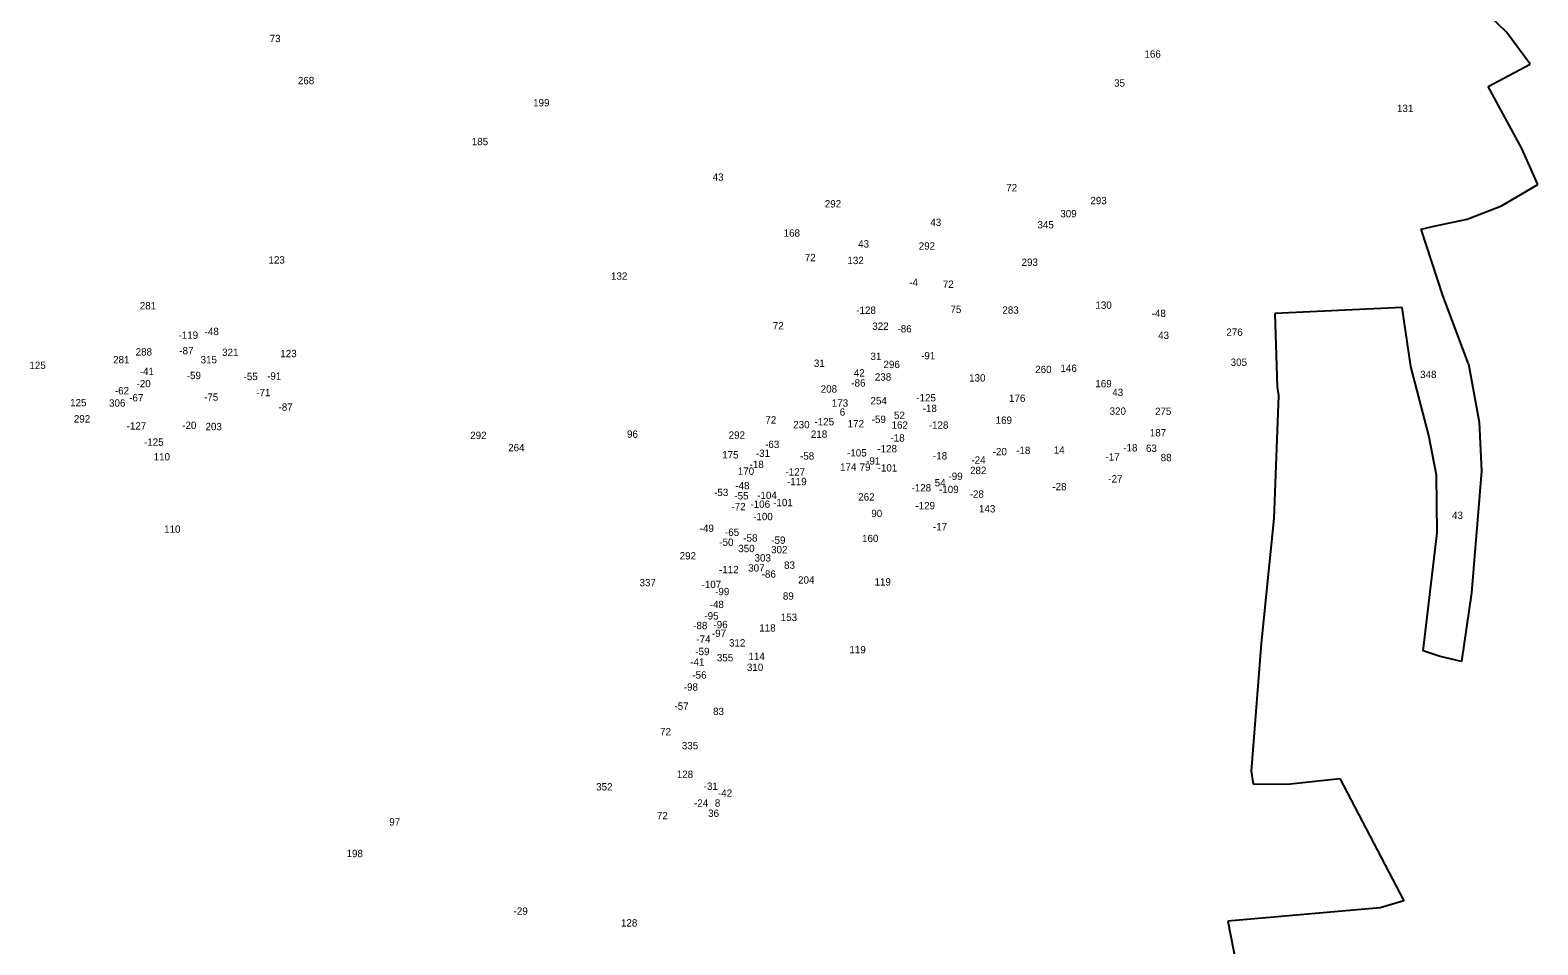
# Model space of a CAD drawing. Extents: x -780116 to -776974, y -980293 to -977147.
# Drawn here: x -778638 to -777335, y -979511 to -978721 of the extents above; entities that cross this region are included whole.
import ezdxf

# ---------------------------------------------------------------- set-up
doc = ezdxf.new("R2010")
doc.units = 0
for name, color, linetype in [('Vrstva 13', 7, 'Continuous'), ('Vrstva 15', 7, 'Continuous'), ('Vrstva 24', 7, 'Continuous')]:
    doc.layers.add(name, color=color, linetype=linetype)

msp = doc.modelspace()

# ---------------------------------------------------------------- linework, layer by layer
at = {"layer": 'Vrstva 13'}
for p, q in [((-777362.22, -978722.53), (-777377.55, -978707.5)), ((-777341.72, -978750.16), (-777362.22, -978722.53)), ((-777377.92, -978769.56), (-777341.72, -978750.16)), ((-777348.79, -978822.96), (-777377.92, -978769.56)), ((-777334.99, -978854.28), (-777348.79, -978822.96)), ((-777366.3, -978872.5), (-777334.99, -978854.28)), ((-777396.05, -978884.27), (-777366.3, -978872.5)), ((-777423.29, -978889.9), (-777396.05, -978884.27)), ((-777435.87, -978892.86), (-777423.29, -978889.9)), ((-777417.23, -978950.19), (-777435.87, -978892.86)), ((-777394.87, -979008.99), (-777417.23, -978950.19))]:
    msp.add_line(p, q, dxfattribs=at)
at = {"layer": 'Vrstva 15'}
for p, q in [((-777452.25, -978960.55), (-777562.39, -978965.5)), ((-777562.39, -978965.5), (-777560.35, -979029.05)), ((-777444.67, -979011.56), (-777452.25, -978960.55)), ((-777429.23, -979071.02), (-777444.67, -979011.56)), ((-777394.87, -979008.99), (-777385.81, -979059.43)), ((-777560.35, -979029.05), (-777559.18, -979036.34)), ((-777559.18, -979036.34), (-777563.26, -979142.8)), ((-777422.67, -979105.2), (-777429.23, -979071.02)), ((-777385.81, -979059.43), (-777383.77, -979101.99)), ((-777421.94, -979155.11), (-777422.67, -979105.2)), ((-777383.77, -979101.99), (-777392.37, -979207.08)), ((-777563.26, -979142.8), (-777574.04, -979250.73)), ((-777434.03, -979257.03), (-777421.94, -979155.11)), ((-777392.37, -979207.08), (-777400.89, -979266.28)), ((-777574.04, -979250.73), (-777582.78, -979360.91)), ((-777419.54, -979262.06), (-777434.03, -979257.03)), ((-777400.89, -979266.28), (-777419.54, -979262.06)), ((-777582.78, -979360.91), (-777581.04, -979372.28)), ((-777548.69, -979371.99), (-777506.15, -979367.33)), ((-777506.15, -979367.33), (-777450.79, -979473.14)), ((-777581.04, -979372.28), (-777548.69, -979371.99)), ((-777450.79, -979473.14), (-777471.19, -979478.97)), ((-777471.19, -979478.97), (-777602.89, -979490.63)), ((-777602.89, -979490.63), (-777592.69, -979542.23))]:
    msp.add_line(p, q, dxfattribs=at)

# ---------------------------------------------------------------- texts
at = {"layer": 'Vrstva 24'}
for s, p in [('73', (-778430.899, -978731.194)), ('166', (-777674.931, -978744.614)), ('268', (-778406.513, -978767.534)), ('35', (-777701.205, -978769.634)), ('199', (-778203.211, -978786.714)), ('131', (-777456.719, -978791.544)), ('185', (-778256.231, -978820.234)), ('43', (-778048.105, -978850.924)), ('72', (-777794.369, -978860.074)), ('292', (-777951.183, -978874.034)), ('309', (-777747.658, -978882.534)), ('293', (-777721.653, -978871.204)), ('43', (-777859.985, -978889.984)), ('345', (-777767.413, -978892.114)), ('168', (-777986.751, -978899.224)), ('43', (-777922.355, -978908.644)), ('72', (-777968.419, -978920.444)), ('292', (-777870.003, -978910.464)), ('123', (-778431.921, -978922.494)), ('132', (-777931.641, -978922.954)), ('293', (-777781.133, -978924.494)), ('132', (-778135.901, -978936.434)), ('-4', (-777878.201, -978941.904)), ('72', (-777849.179, -978943.484)), ('281', (-778543.111, -978962.074)), ('-128', (-777923.965, -978965.964)), ('75', (-777842.619, -978965.214)), ('283', (-777797.733, -978965.774)), ('130', (-777717.316, -978961.584)), ('-48', (-777668.698, -978968.664)), ('-48', (-778487.098, -978984.294)), ('72', (-777996.109, -978979.364)), ('322', (-777910.153, -978979.744)), ('-86', (-777888.359, -978981.994)), ('276', (-777604.178, -978984.904)), ('-119', (-778509.653, -978987.494)), ('43', (-777663.105, -978987.674)), ('281', (-778566.171, -979008.684)), ('288', (-778546.703, -979001.944)), ('-87', (-778508.973, -979000.914)), ('315', (-778490.571, -979008.694)), ('321', (-778471.961, -979002.344)), ('123', (-778421.681, -979003.374)), ('31', (-777960.633, -979011.764)), ('31', (-777911.683, -979005.784)), ('296', (-777900.443, -979012.794)), ('-91', (-777867.967, -979005.204)), ('305', (-777600.427, -979010.874)), ('125', (-778638.511, -979013.584)), ('-41', (-778543.146, -979018.844)), ('-59', (-778502.539, -979022.334)), ('-55', (-778453.429, -979023.214)), ('-91', (-778433.107, -979022.784)), ('42', (-777926.025, -979020.074)), ('238', (-777907.893, -979023.594)), ('130', (-777826.456, -979024.404)), ('260', (-777769.328, -979017.104)), ('146', (-777747.511, -979016.044)), ('348', (-777436.723, -979021.444)), ('-62', (-778564.629, -979035.464)), ('-20', (-778545.953, -979029.344)), ('-71', (-778442.461, -979037.074)), ('208', (-777954.717, -979034.004)), ('-86', (-777928.279, -979028.784)), ('169', (-777717.421, -979029.384)), ('43', (-777702.745, -979036.944)), ('125', (-778603.351, -979045.794)), ('306', (-778569.698, -979046.134)), ('-67', (-778552.263, -979041.584)), ('-75', (-778487.563, -979040.984)), ('-87', (-778423.213, -979049.614)), ('173', (-777945.105, -979046.124)), ('254', (-777911.683, -979044.094)), ('-125', (-777872.085, -979041.594)), ('-18', (-777866.577, -979050.774)), ('176', (-777791.985, -979041.974)), ('292', (-778600.123, -979059.824)), ('72', (-778002.529, -979060.734)), ('230', (-777978.428, -979064.824)), ('-125', (-777960.095, -979062.284)), ('6', (-777938.287, -979053.894)), ('172', (-777931.395, -979064.014)), ('-59', (-777910.639, -979060.244)), ('162', (-777893.501, -979065.154)), ('52', (-777891.385, -979056.764)), ('-128', (-777861.305, -979065.204)), ('169', (-777803.541, -979060.934)), ('320', (-777705.058, -979053.134)), ('275', (-777665.817, -979053.304)), ('-127', (-778554.509, -979065.934)), ('-20', (-778506.463, -979065.354)), ('203', (-778486.327, -979066.474)), ('292', (-778257.563, -979074.084)), ('96', (-778122.085, -979073.004)), ('292', (-778034.243, -979073.814)), ('218', (-777963.191, -979073.054)), ('-18', (-777894.417, -979076.284)), ('187', (-777670.346, -979071.844)), ('-125', (-778539.475, -979079.934)), ('264', (-778224.803, -979084.634)), ('175', (-778039.835, -979090.884)), ('-31', (-778010.707, -979089.554)), ('-63', (-778002.749, -979081.834)), ('-105', (-777931.939, -979089.174)), ('-128', (-777905.745, -979085.614)), ('-20', (-777806.083, -979088.124)), ('-18', (-777785.787, -979087.034)), ('14', (-777753.313, -979086.664)), ('-18', (-777693.257, -979084.844)), ('63', (-777673.635, -979085.204)), ('110', (-778531.154, -979092.624)), ('-18', (-778016.167, -979099.174)), ('-58', (-777972.579, -979091.884)), ('174', (-777937.985, -979101.434)), ('79', (-777921.09, -979101.504)), ('-91', (-777915.477, -979096.174)), ('-101', (-777905.507, -979102.154)), ('-18', (-777857.697, -979091.744)), ('282', (-777825.663, -979104.404)), ('-24', (-777824.479, -979095.414)), ('-17', (-777708.581, -979092.704)), ('88', (-777660.895, -979093.244)), ('170', (-778026.351, -979104.984)), ('-127', (-777985.149, -979105.634)), ('-119', (-777983.783, -979113.974)), ('54', (-777856.215, -979114.994)), ('-99', (-777844.269, -979109.394)), ('-27', (-777706.163, -979111.654)), ('-53', (-778046.829, -979123.364)), ('-55', (-778029.339, -979126.274)), ('-48', (-778028.468, -979117.534)), ('-104', (-778009.579, -979125.834)), ('262', (-777922.263, -979127.254)), ('-128', (-777876.245, -979119.374)), ('-109', (-777852.459, -979120.764)), ('-28', (-777825.919, -979124.774)), ('-28', (-777754.519, -979118.364)), ('-72', (-778031.833, -979135.604)), ('-106', (-778015.439, -979133.554)), ('-101', (-777995.777, -979132.094)), ('90', (-777910.96, -979141.554)), ('-129', (-777872.885, -979134.824)), ('143', (-777817.91, -979137.514)), ('43', (-777409.175, -979143.134)), ('110', (-778522.114, -979155.054)), ('-49', (-778059.279, -979154.344)), ('-100', (-778013.084, -979144.204)), ('-17', (-777857.721, -979152.974)), ('-50', (-778042.343, -979166.374)), ('-65', (-778037.419, -979157.774)), ('-58', (-778021.609, -979162.724)), ('-59', (-777997.419, -979164.614)), ('160', (-777918.956, -979163.124)), ('292', (-778076.593, -979178.164)), ('350', (-778025.928, -979171.814)), ('303', (-778011.867, -979179.914)), ('302', (-777997.587, -979172.824)), ('-112', (-778042.583, -979190.044)), ('307', (-778017.383, -979188.614)), ('-86', (-778005.719, -979193.914)), ('83', (-777986.355, -979186.184)), ('337', (-778111.298, -979201.294)), ('-107', (-778057.654, -979202.884)), ('204', (-777974.277, -979198.994)), ('119', (-777908.179, -979200.694)), ('-48', (-778050.618, -979220.154)), ('-99', (-778045.939, -979209.004)), ('89', (-777987.375, -979212.874)), ('-95', (-778055.239, -979230.044)), ('153', (-777989.251, -979231.274)), ('-88', (-778064.899, -979238.374)), ('-97', (-778048.713, -979245.124)), ('-96', (-778047.369, -979237.544)), ('118', (-778007.809, -979240.434)), ('-74', (-778062.233, -979250.154)), ('312', (-778033.951, -979253.334)), ('119', (-777929.909, -979259.194)), ('-41', (-778067.456, -979269.904)), ('-59', (-778063.069, -979260.794)), ('355', (-778044.433, -979266.164)), ('114', (-778017.139, -979265.094)), ('-56', (-778065.609, -979281.134)), ('310', (-778018.486, -979274.454)), ('-98', (-778073.029, -979291.474)), ('-57', (-778081.083, -979307.964)), ('83', (-778047.695, -979312.564)), ('72', (-778093.489, -979330.064)), ('335', (-778074.713, -979342.114)), ('352', (-778148.723, -979377.714)), ('128', (-778079.081, -979366.944)), ('-31', (-778055.867, -979377.194)), ('-42', (-778043.478, -979383.174)), ('72', (-778096.249, -979402.614)), ('-24', (-778064.169, -979391.774)), ('36', (-778051.995, -979400.524)), ('8', (-778046.207, -979391.704)), ('97', (-778327.53, -979408.024)), ('198', (-778364.441, -979435.334)), ('-29', (-778220.079, -979485.074)), ('128', (-778127.321, -979495.274))]:
    msp.add_text(s, height=6.336, dxfattribs=at).set_placement(p)

doc.saveas('drawing.dxf')
